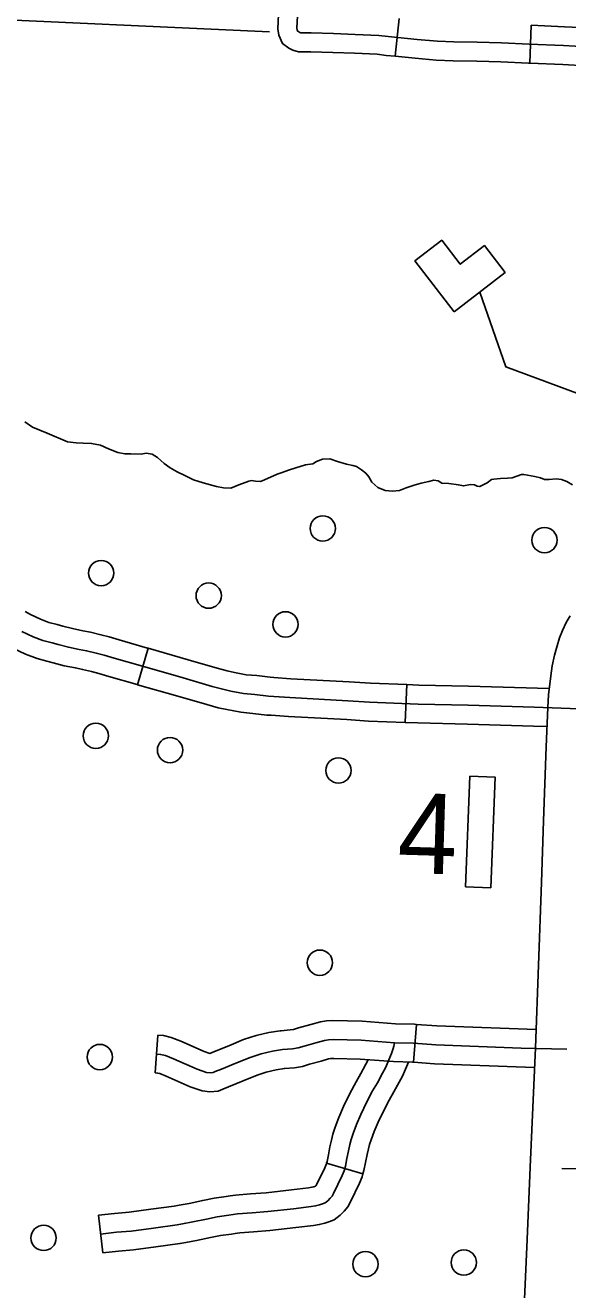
# Model space of a CAD drawing. Extents: x 653372 to 905732, y 627442 to 787275.
# Drawn here: x 674841 to 676986, y 764534 to 769532 of the extents above; entities that cross this region are included whole.
import ezdxf

# ---------------------------------------------------------------- set-up
doc = ezdxf.new("R2010")
doc.units = 0
for name, color, linetype in [('10', 7, 'Continuous'), ('31', 7, 'Continuous'), ('32', 7, 'Continuous'), ('35', 7, 'Continuous'), ('5', 7, 'Continuous'), ('56', 7, 'Continuous'), ('58', 7, 'Continuous')]:
    doc.layers.add(name, color=color, linetype=linetype)

msp = doc.modelspace()

# ---------------------------------------------------------------- linework, layer by layer
at = {"layer": '10'}
msp.add_lwpolyline([(676814.7, 764497.3), (676825.6, 764732.2), (676837.4, 765019), (676857.7, 765490), (676881.9, 766144.4), (676890.1, 766387.1), (676900.9, 766680.7), (676906.5, 766836.2), (676909.5, 766885.9), (676918.5, 766961.2), (676924.4, 767000.2), (676934, 767042.5), (676943.8, 767079.8), (676953, 767110.6), (676964.6, 767139.3), (676979, 767170.9), (676994.9, 767198.5)], dxfattribs=at)
at = {"layer": '31'}
for p, q in [((675285.3, 766925.6), (675326.6, 767069.8)), ((675326.6, 767069.8), (675326.6, 767069.8)), ((676349.1, 766926), (676343.5, 766776.1)), ((676387.3, 765583), (676375.7, 765433.4)), ((675355, 765391), (675366, 765540.6)), ((675864.4, 765408.6), (675864.4, 765408.6)), ((676032, 765034.1), (676176, 764992.1)), ((675147.3, 764679.8), (675130.4, 764828.9)), ((675130.4, 764828.9), (675130.4, 764828.9))]:
    msp.add_line(p, q, dxfattribs=at)
for points in [[(674841.4, 767215.3), (674862.5, 767202.6), (674900.9, 767184.6), (674934.3, 767172.1), (674967.8, 767163), (674990.3, 767156.5), (675028.3, 767147.2), (675068.7, 767138.8), (675099.6, 767133), (675140.6, 767123), (675173, 767114.3), (675213, 767102.8), (675324.9, 767070.3), (675326.6, 767069.8)], [(674827.2, 767136.3), (674871.9, 767115.4), (674911.3, 767100.7), (674947.5, 767090.8), (674970.9, 767084), (675011.9, 767074), (675054.2, 767065.3), (675083.7, 767059.7), (675122, 767050.4), (675152.8, 767042), (675192.2, 767030.7), (675304.1, 766998.3), (675464.9, 766952.2), (675579.8, 766919), (675622, 766907.6), (675653.5, 766900.6), (675703.9, 766891), (675748.4, 766886.9), (675802.9, 766880.5), (675886.6, 766874.6), (676116.7, 766862.3), (676202.6, 766856.4), (676395, 766849.2), (676591.5, 766844.6), (676852.4, 766836.9), (677031.3, 766830.1)], [(674764.2, 767086.7), (674791.9, 767070), (674842.8, 767046.2), (674888.3, 767029.2), (674927.2, 767018.6), (674951.6, 767011.5), (674995.4, 767000.8), (675039.6, 766991.7), (675067.9, 766986.3), (675103.3, 766977.7), (675132.6, 766969.8), (675171.4, 766958.6), (675283.3, 766926.2), (675285.3, 766925.6)], [(675326.6, 767069.8), (675485.6, 767024.3), (675600, 766991.2), (675640, 766980.4), (675668.7, 766974), (675714.4, 766965.3), (675756.1, 766961.5), (675809.9, 766955.2), (675824.3, 766954.2)], [(675824.4, 766954.2), (675891.2, 766949.5), (676121.3, 766937.2), (676206.6, 766931.3), (676349.1, 766926)], [(675813.8, 766804.6), (675796, 766805.8), (675740.7, 766812.3), (675693.5, 766816.6), (675638.3, 766827.1), (675604.1, 766834.8), (675559.6, 766846.8), (675444.2, 766880.1), (675285.3, 766925.6)], [(676349.1, 766926), (676397.2, 766924.2), (676593.5, 766919.6), (676912.4, 766910.1)], [(676343.5, 766776.1), (676198.6, 766781.5), (676112.1, 766787.5), (675881.9, 766799.8), (675813.8, 766804.6)], [(676343.5, 766776.1), (676392.7, 766774.3), (676589.5, 766769.7), (676849.9, 766761.9), (676903.7, 766759.9)], [(675853.2, 765558.2), (675888.6, 765560.9), (675902.1, 765563), (675921.8, 765569.3), (675970.5, 765582.7), (676008.6, 765593.4), (676031.7, 765596.7), (676056.6, 765598.7), (676172.7, 765596), (676304.5, 765585.7), (676380.6, 765583.5), (676387.2, 765583)], [(675366, 765540.6), (675388.1, 765539), (675418.4, 765531.5), (675456.5, 765516.4), (675548.6, 765476.2), (675570.4, 765468.5), (675589.1, 765475.9), (675646, 765498.9), (675704.6, 765522.8), (675753.5, 765539.6), (675804.8, 765550.6), (675848.8, 765557.9), (675853.1, 765558.2)], [(676387.3, 765583), (676468.2, 765576.7), (676860.4, 765562.5)], [(675138.9, 764754.3), (675201.9, 764761.5), (675260.4, 764766.3), (675348, 764777.9), (675441.2, 764790.8), (675462.5, 764794.3), (675503.4, 764802.1), (675557.9, 764813.7), (675600.5, 764822.1), (675645.5, 764828.8), (675680.9, 764833.6), (675737.7, 764838.1), (675800.7, 764842.9), (675902.1, 764854.1), (675970.9, 764863.1), (675988.7, 764865.3), (676003.8, 764869.4), (676016, 764873.6), (676026.2, 764877.4), (676036.9, 764885.4), (676046.9, 764895.6), (676054.5, 764904.4), (676060, 764915), (676094.1, 764985.5), (676101.6, 765004.8), (676107, 765023.3), (676113.1, 765052.4), (676119.2, 765083.8), (676124.8, 765108.3), (676130, 765128.7), (676137.3, 765151.4), (676150.8, 765187.2), (676168, 765227.3), (676191.7, 765276.6), (676214.6, 765320.1), (676233.2, 765352.6), (676253.5, 765390.2), (676264.9, 765411.4), (676289.1, 765467.7), (676295.6, 765487.3), (676298, 765496.9), (676300.5, 765510.7)], [(675360.5, 765465.8), (675376.3, 765464.6), (675395.5, 765459.9), (675427.7, 765447.2), (675521.1, 765406.3), (675557.7, 765393.5), (675572.2, 765391.7), (675584, 765392.7), (675592.4, 765396.6), (675616.9, 765406.2), (675674.3, 765429.4), (675731, 765452.6), (675773.6, 765467.2), (675818.8, 765476.9), (675857.7, 765483.4), (675897.2, 765486.3), (675919.5, 765489.8), (675943.2, 765497.4), (675990.6, 765510.5), (676024.1, 765519.9), (676040, 765522.1), (676058.7, 765523.7), (676168.9, 765521), (676300.5, 765510.7), (676376.6, 765508.6), (676463.9, 765501.8), (676801.6, 765489.6), (676982.6, 765485)], [(676375.7, 765433.4), (676372.6, 765433.7), (676296.5, 765435.8), (676165, 765446.1), (676060.9, 765448.6), (676048.4, 765447.6), (676039.5, 765446.3), (676010.7, 765438.2), (675964.6, 765425.5), (675936.8, 765416.6), (675905.8, 765411.8), (675864.4, 765408.6)], [(675864.4, 765408.6), (675866.7, 765408.8), (675832.8, 765403.2), (675793.7, 765394.8), (675757.4, 765382.3), (675702.5, 765359.9), (675644.7, 765336.5), (675621.9, 765327.6), (675603.6, 765319.1), (675570.8, 765316.2), (675540.4, 765320.1), (675493.7, 765336.5), (675398.8, 765377.9), (675372.7, 765388.3), (675364.5, 765390.3), (675355, 765391)], [(676032, 765034.1), (676034.2, 765041.6), (676039.6, 765067.3), (676045.9, 765099.3), (676051.9, 765125.8), (676057.8, 765149.3), (676066.4, 765176.2), (676081.3, 765215.3), (676099.7, 765258.3), (676124.7, 765310.3), (676148.8, 765356.2), (676167.7, 765389.1), (676197, 765443.6)], [(676176, 764992.1), (676179.8, 765005.1), (676186.6, 765037.4), (676192.6, 765068.2), (676197.8, 765090.8), (676202.1, 765108.1), (676208.1, 765126.7), (676220.4, 765159.1), (676236.3, 765196.3), (676258.7, 765242.9), (676280.3, 765283.9), (676298.8, 765316.2), (676319.5, 765354.7), (676332.5, 765378.7), (676356.4, 765434.1)], [(676375.7, 765433.4), (676459.6, 765426.9), (676854.4, 765412.6)], [(675650.7, 764905.2), (675672.8, 764908.2), (675731.9, 764912.9), (675793.8, 764917.5), (675893.1, 764928.5), (675961.3, 764937.5), (675974.2, 764939.1), (675982, 764941.2), (675988.9, 764943.6), (675991.7, 764946.4), (675991.9, 764946.7), (675993, 764948.6), (676025.3, 765015.5), (676030.5, 765029), (676032, 765034.1)], [(677236.7, 765009.6), (676962.3, 765013.7)], [(676176, 764992.1), (676172.7, 764980.5), (676162.9, 764955.5), (676127, 764881.3), (676117, 764862.1), (676102.1, 764844.7), (676086.3, 764828.8), (676062.8, 764811.1), (676041.3, 764802.9), (676025.5, 764797.6), (676003.2, 764791.6), (675980.5, 764788.7), (675911.1, 764779.6), (675807.6, 764768.2), (675743.5, 764763.4), (675689, 764759), (675671.1, 764756.5)], [(675130.4, 764828.9), (675194.6, 764836.1), (675252.4, 764840.9), (675337.9, 764852.3), (675430, 764864.9), (675449.3, 764868.1), (675488.6, 764875.6), (675542.8, 764887.1), (675587.8, 764896), (675635, 764903), (675650.8, 764905.2)], [(675671.1, 764756.5), (675656.1, 764754.5), (675613.3, 764748.2), (675573, 764740.2), (675518.2, 764728.6), (675475.7, 764720.5), (675452.5, 764716.6), (675358, 764703.6), (675268.5, 764691.7), (675209.3, 764686.8), (675147.3, 764679.8)]]:
    msp.add_lwpolyline(points, dxfattribs=at)
at = {"layer": '32'}
for p, q in [((676304.1, 769409.6), (676319, 769558.8)), ((676835.4, 769382.2), (676841.8, 769532))]:
    msp.add_line(p, q, dxfattribs=at)
for points in [[(675847.1, 769622.7), (675847.1, 769615.1), (675842.5, 769574.4), (675840.1, 769518.3), (675844.1, 769493.1), (675857.8, 769459.6), (675882.6, 769441.9), (675898.5, 769433.4), (675920.9, 769427.1), (675970.1, 769427), (676057.6, 769424.4), (676142.6, 769421.3), (676232.4, 769417.5), (676267.8, 769413.2), (676304.1, 769409.6)], [(675917.4, 769568.7), (675915.4, 769522.5), (675916.8, 769513.4), (675919, 769508.2), (675922.3, 769505.8), (675926.8, 769503.4), (675931.3, 769502.1), (675971.2, 769502), (676060.1, 769499.4), (676145.5, 769496.2), (676238.5, 769492.3), (676276, 769487.7), (676390.3, 769476.3), (676470.5, 769468.8), (676535.4, 769466.3), (676628.3, 769465.2), (676723.6, 769462.3), (676833.5, 769457.3), (676969.6, 769451.5), (677060.7, 769446.5)], [(676841.8, 769532), (676973.3, 769526.4), (677064.5, 769521.4), (677098, 769519.9), (677138.8, 769520.8), (677175.2, 769522.2), (677196.3, 769520.7), (677229.9, 769515.8), (677262.5, 769494.9), (677287.7, 769468.1), (677299.1, 769443.5), (677306.6, 769420), (677309.9, 769385.7), (677309.4, 769347.4), (677305.1, 769287.6)], [(676304.1, 769409.6), (676383.1, 769401.7), (676465.5, 769393.9), (676533.5, 769391.3), (676626.7, 769390.2), (676720.8, 769387.4), (676830.2, 769382.4), (676835.4, 769382.2)], [(676835.4, 769382.2), (676966, 769376.6), (677056.9, 769371.6), (677096.2, 769369.8), (677143.4, 769370.8), (677159.7, 769371.5), (677159.5, 769353.7), (677155.5, 769298.3)]]:
    msp.add_lwpolyline(points, dxfattribs=at)
at = {"layer": '35'}
for points in [[(674839.8, 767964.3), (674869.9, 767943.5), (674927.4, 767920.1), (675008.6, 767886.1), (675041.9, 767882.3)], [(675041.9, 767882.3), (675069.8, 767880.6), (675103.2, 767879.6), (675138.3, 767872.2), (675170.4, 767858.6), (675207, 767844), (675234.8, 767838.6), (675259.2, 767837.9), (675299.8, 767837.5), (675318.9, 767840.6), (675342.3, 767837.2), (675364.5, 767823.9), (675390.9, 767800.5), (675413.8, 767782.6), (675442.2, 767766.4), (675471.6, 767752), (675506.4, 767735.6), (675544.6, 767723.6), (675597.4, 767709.3), (675625.3, 767704), (675654.1, 767702.2), (675685.3, 767715.7), (675725.5, 767730.8), (675735.4, 767732.3), (675751.6, 767730), (675770.6, 767728.5), (675787, 767735.3), (675837.4, 767758.1), (675856.6, 767764.8), (675882.1, 767773.1), (675910.4, 767783.1), (675948.7, 767794.6), (675978.7, 767799.1), (675992.5, 767807.7), (676016.6, 767816.9), (676045.5, 767817.9), (676075.1, 767807.9), (676110.9, 767796.9), (676136, 767791.7), (676150.4, 767788.5), (676170.7, 767774.3), (676187.5, 767761.2), (676199.7, 767747.3), (676211.7, 767726.1), (676234.6, 767704.7), (676264.1, 767693.8), (676292.9, 767691.2), (676320.1, 767693.9), (676347.5, 767704), (676378.5, 767713.9)], [(676378.5, 767713.9), (676406.7, 767722.1), (676437.1, 767729.3), (676456.7, 767734.6), (676473.8, 767731.8), (676488, 767722.8), (676515.7, 767721.5), (676553.4, 767715), (676573.2, 767711.7), (676601.2, 767716.7), (676616.7, 767715.8), (676628.3, 767710.9), (676638.2, 767708.8), (676666.6, 767724.2), (676683.9, 767736.2), (676693.9, 767737.4), (676719.3, 767740.6), (676747.8, 767741.7), (676765.9, 767743.4), (676803.2, 767756.3), (676812.7, 767756), (676855.1, 767748.4), (676877.8, 767743.2), (676894.5, 767737.2), (676912.4, 767736.7), (676940.2, 767738.8), (676960.5, 767736.9), (676981.9, 767729), (677004.8, 767715.9)]]:
    msp.add_lwpolyline(points, dxfattribs=at)
at = {"layer": '5'}
msp.add_lwpolyline([(675807.3, 769505.7), (674538.7, 769563.7)], dxfattribs=at)
at = {"layer": '56'}
msp.add_lwpolyline([(676682.1, 766123), (676582.1, 766126.9), (676599.1, 766564), (676699.1, 766560.1)], close=True, dxfattribs=at)
for centre in [(676017.4, 767543.3), (676893.8, 767497), (675141.3, 767366.9), (675566.4, 767277.7), (675870, 767164.1), (675120.2, 766723.9), (675413.6, 766667.2), (676079.2, 766586.6), (676005.9, 765826.9), (675136, 765454), (674913.8, 764739), (676186.2, 764635.4), (676574.9, 764641.6)]:
    msp.add_circle(centre, 50, dxfattribs=at)
at = {"layer": '58'}
msp.add_lwpolyline([(676537.3, 768399.6), (676738.2, 768555.1), (676656.2, 768661), (676561.1, 768587.5), (676487.7, 768682.4), (676381.9, 768600.5)], close=True, dxfattribs=at)
msp.add_lwpolyline([(676637.8, 768477.3), (676740.9, 768181.4), (677149.9, 768030.6)], dxfattribs=at)

# ---------------------------------------------------------------- texts
at = {"layer": '56'}
msp.add_text('4', height=316.8, rotation=358.28, dxfattribs=at).set_placement((676310, 766182.6))

doc.saveas('drawing.dxf')
